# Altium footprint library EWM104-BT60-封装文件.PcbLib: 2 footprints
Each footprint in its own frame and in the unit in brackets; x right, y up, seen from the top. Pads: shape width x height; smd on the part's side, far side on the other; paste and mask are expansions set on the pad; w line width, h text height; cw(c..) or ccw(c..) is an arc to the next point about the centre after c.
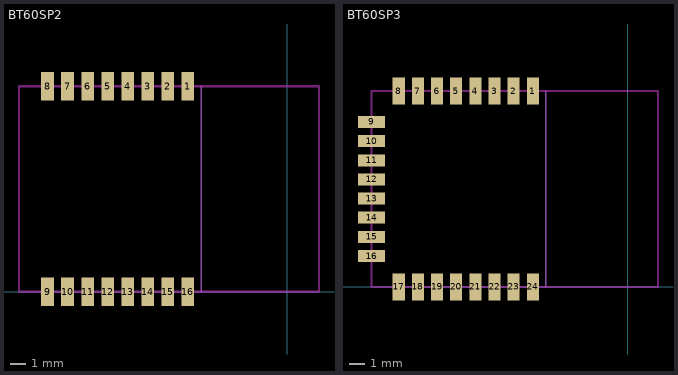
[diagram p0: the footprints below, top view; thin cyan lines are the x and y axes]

## BT60SP2 [mm]
pads (16):
  rect 0.8x1.8 smd paste+0 mask+0: 1(-6.295,13) 2(-7.565,13) 3(-8.835,13) 4(-10.105,13) 5(-11.375,13) 6(-12.645,13) 7(-13.915,13) 8(-15.185,13) 9(-15.185,0) 10(-13.915,0) 11(-12.645,0) 12(-11.375,0) 13(-10.105,0) 14(-8.835,0) 15(-7.565,0) 16(-6.295,0)
Keep-Out Layer:
  lines w0.15: -16.99,0 -16.99,13 ; -16.99,0 -16.99,13 ; -16.99,0 2.01,0 ; -16.99,0 2.01,0 ; -16.99,13 2.01,13 ; -16.99,13 2.01,13 ; 2.01,0 2.01,13 ; 2.01,0 2.01,13
Mechanical 7:
  lines w0.1: -5.451,0 -5.451,13

## BT60SP3 [mm]
pads (24):
  rect 0.8x1.8 smd paste+0 mask+0: 1(-6.295,13) 2(-7.565,13) 3(-8.835,13) 4(-10.105,13) 5(-11.375,13) 6(-12.645,13) 7(-13.915,13) 8(-15.185,13) 17(-15.185,0) 18(-13.915,0) 19(-12.645,0) 20(-11.375,0) 21(-10.105,0) 22(-8.835,0) 23(-7.565,0) 24(-6.295,0)
  rect 1.8x0.8 smd paste+0 mask+0: 9(-16.99,10.945) 10(-16.99,9.675) 11(-16.99,8.405) 12(-16.99,7.135) 13(-16.99,5.865) 14(-16.99,4.595) 15(-16.99,3.325) 16(-16.99,2.055)
Keep-Out Layer:
  lines w0.15: -16.99,0 2.01,0 ; -16.99,0 2.01,0 ; -16.99,0 -16.99,13 ; -16.99,0 -16.99,13 ; -16.99,13 2.01,13 ; -16.99,13 2.01,13 ; 2.01,0 2.01,13 ; 2.01,0 2.01,13
Mechanical 7:
  lines w0.1: -5.451,0 -5.451,13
